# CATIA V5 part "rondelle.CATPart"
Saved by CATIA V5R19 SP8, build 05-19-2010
Part number: rondelle(artifice animation)
Bounding box of the stored display mesh (mm): x -15 to 15, y -15 to 15, z 0 to 20
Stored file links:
  G:\EU_thinkMotion\CFAO_2010\St2M_groupe2\St2M_groupe2\npeyre\npeyre\rondelle.CATPart
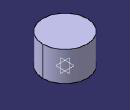
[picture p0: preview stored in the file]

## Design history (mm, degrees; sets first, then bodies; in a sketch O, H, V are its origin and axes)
Parameters
  diametrerondelle = 30 mm
Body1 (main body)
  Sketch1 on xy-plane, origin (0, 0, 0), H (1, 0, 0), V (0, 1, 0)
    circle A1 centre (0, 0) radius 15
    radius A1 = 15 {= diametrerondelle /2}
  Pad1: profile Sketch1, direction (0, 0, 1), length 20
